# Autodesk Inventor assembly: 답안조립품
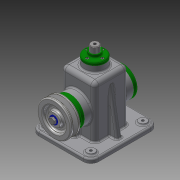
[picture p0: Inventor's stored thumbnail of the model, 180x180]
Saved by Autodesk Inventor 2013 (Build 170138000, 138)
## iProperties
Created: 2016-01
Part Number: 답안조립품
Document SubType Name: Assembly
Designer: Administrator
Author: Administrator
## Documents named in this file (19)
- C:\Users\Administrator\Desktop\460127V1005\답안조립품.iam
- C:\Users\Administrator\Desktop\460127V1005\1본체.ipt
- C:\Users\Administrator\Desktop\460127V1005\V-벨트풀리.ipt
- C:\Users\Administrator\Desktop\460127V1005\고정핀.ipt
- C:\Users\Administrator\Desktop\460127V1005\뒤커버.ipt
- C:\Users\Administrator\Desktop\460127V1005\링크.ipt
- C:\Users\Administrator\Desktop\460127V1005\멈춤링 6 x 5.ipt
- C:\Users\Administrator\Desktop\460127V1005\멈춤링 15 x 1.ipt
- C:\Users\Administrator\Desktop\460127V1005\베어링 15 x 35 x 11.ipt
- C:\Users\Administrator\Desktop\460127V1005\볼트 M3 x 8.ipt
- C:\Users\Administrator\Desktop\460127V1005\볼트 M4 x 10.ipt
- C:\Users\Administrator\Desktop\460127V1005\볼트 M6 x 12.ipt
- C:\Users\Administrator\Desktop\460127V1005\상부부시.ipt
- C:\Users\Administrator\Desktop\460127V1005\슬라이드바.ipt
- C:\Users\Administrator\Desktop\460127V1005\앞커버.ipt
- C:\Users\Administrator\Desktop\460127V1005\오일실 15 25 7.ipt
- C:\Users\Administrator\Desktop\460127V1005\와셔.ipt
- C:\Users\Administrator\Desktop\460127V1005\키 5 x 5 x 14.ipt
- C:\Users\Administrator\Desktop\460127V1005\편심축.ipt
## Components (16 placed, 6 different names)
1. 1본체:1
2. V-벨트풀리:1 — 각도:2
3. 고정핀:1
4. ISO 4018 M6 x 12:1
5. ISO 4762 M3 x 8:1
6. ISO 4762 M3 x 8:4
7. ISO 4762 M3 x 8:5
8. ISO 4762 M3 x 8:6
9. ISO 4762 M4 x 10:1
10. ISO 4762 M4 x 10:3
11. ISO 4762 M4 x 10:4
12. ISO 4762 M4 x 10:5
13. ISO 4762 M4 x 10:2
14. ISO 4762 M4 x 10:6
15. ISO 4762 M4 x 10:7
16. ISO 4762 M4 x 10:8
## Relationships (1: Angle 1)
- 각도:2 [Angle]: V-벨트풀리:1
